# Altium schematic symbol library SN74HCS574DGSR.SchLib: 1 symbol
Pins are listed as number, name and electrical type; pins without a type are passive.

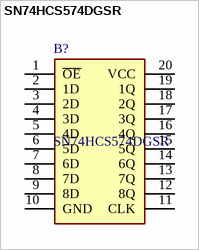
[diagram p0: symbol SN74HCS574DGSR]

## SN74HCS574DGSR
designator B?
Flip-Flops Octal edge-triggered D-type flip-flops w; Manufacturer_Name: Texas Instruments; Geometry.Height: 1.1mm
footprint SOP50P490X110-20N
pins: 1 ~{OE}, 2 1D, 3 2D, 4 3D, 5 4D, 6 5D, 7 6D, 8 7D, 9 8D, 10 GND, 11 CLK, 12 8Q, 13 7Q, 14 6Q, 15 5Q, 16 4Q, 17 3Q, 18 2Q, 19 1Q, 20 VCC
